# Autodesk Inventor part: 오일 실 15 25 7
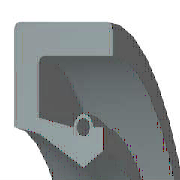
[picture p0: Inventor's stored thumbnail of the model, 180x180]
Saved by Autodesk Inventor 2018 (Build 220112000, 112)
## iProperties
Created: 2012-02
Part Number: 오일 실 15 25 7
Material: 고무
Description: 오일-실
Document SubType Name: Modeling
Standard: KS B 2804
Designer: mduedu
Standards Organization: KS
Language: ko-KR
Size Designation: S - 15 25 7
Categories: <MemberInstance><Categories><Category DisplayName="샤프트 부품" InternalName="7f7aeb1f-a693-4053-b835-cee3144e0d98" Mnemonic="SHFT"><Category DisplayName="실링" Intern
Density: 0.93 g/cm^3
Appearance: 고무 - 검은색 - 버전 1.1
IsCustomPart: 1
Author: mduedu
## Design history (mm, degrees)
revolve "본체" stored, may be unused: angle "d17" = 90 deg
revolve "스프링1" stored, may be unused: angle "d18" = 90 deg
body "Solid1"
sketch "스케치1"
  geometry: L1 (0, 12.5)-(7, 12.5); L2 (7, 12.5)-(7, 11.25); L3 (7, 11.25)-(1.75, 11.25); L4 (0, 12.5)-(0, 9.6); L5 (0, 9.6)-(1.75, 9.25); L6 (1.75, 9.25)-(4.9, 7.5); L7 (4.9, 7.5)-(0, 7.5); L8 (6.3, 8.375)-(6.3, 9.6); L9 (0, 0)-(9.586, 0) reference; L10 (4.9, 7.5)-(6.3, 8.375); L11 (0, 18)-(0, -3) reference; L12 (-1.917, 0)-(11.503, 0) reference; L13 (4.2, 9.6)-(1.75, 10.09); L14 (1.75, 10.09)-(1.75, 11.25); L15 (6.3, 9.6)-(5.6, 9.6); C1 r 0.455 at (4.9, 9.6); A1 r 0.7 centre (4.9, 9.6) between (5.6, 9.6) and (4.2, 9.6)
  constraints: 26 end point, 5 horizontal alignment, 4 perpendicular, 2 centre point, 2 collinear, 2 horizontal, 2 parallel, 2 point on circle, 2 point on line, 2 vertical alignment, 1 coincident
  dimensions: "d0" = 25 diameter of L1 L9 (= SD2); "d1" = 16.75 diameter of L8.start L9 (= ABDM); "d2" = 1.25 distance of L1.end L2.end (computed from SD); "d3" = 0.91 diameter of C1 (= SPDI); "d4" = 1.4 diameter of A1 (= SPDA); "d5" = 15 diameter of L6.end L9 (= NND); "d6" = 18.5 diameter of L5.end L9 (= TKDM); "d7" = 19.2 diameter of L4.end L9 (= HLDM); "d8" = 4.9 distance from line of C1.centre L4 (= SPDST); "d9" = 6.3 distance between parallel lines of L8 L4 (= SDI); "d10" = 7 distance between parallel lines of L2 L4 (= SWDT); "d12" = 1.75 distance between parallel lines of L14 L4 (= SD)
fillet "모깎기1" dims "d11" = 0.3 (= RR)
other parameters: "SD2" = 25 [user parameter; used in 1 equation term], "SWDT" = 7 [user parameter; used in 1 equation term], "RR" = 0.3 [user parameter; used in 1 equation term], "SD" = 1.75 [user parameter; used in 2 equation terms], "NND" = 15 [user parameter; used in 1 equation term], "SPDA" = 1.4 [user parameter; used in 1 equation term], "SPDI" = 0.91 [user parameter; used in 1 equation term], "TKDM" = 18.5 [user parameter; used in 1 equation term], "HLDM" = 19.2 [user parameter; used in 1 equation term], "ABDM" = 16.75 [user parameter; used in 1 equation term], "SDI" = 6.3 [user parameter; used in 1 equation term], "SPDST" = 4.9 [user parameter; used in 1 equation term], "d13" = 0, "d14" = 0, "d15" = 0, "LAB" = 0.35 [user parameter]
